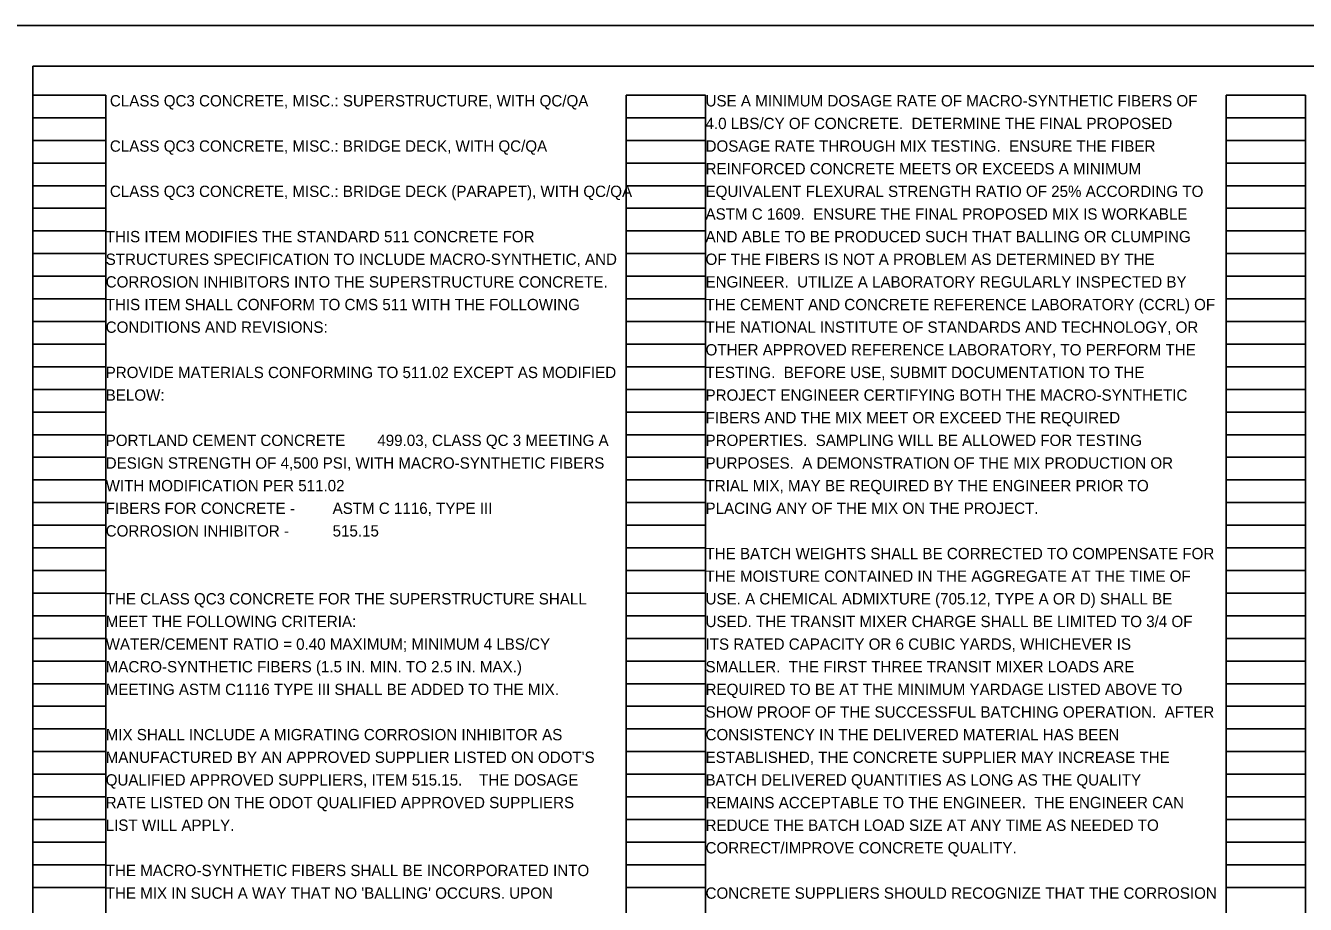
# Model space of a CAD drawing. Extents: x -14.8 to 34, y 0 to 43.2.
# Drawn here: x 1.91 to 17.74, y 11.13 to 22 of the extents above; entities that cross this region are included whole.
import ezdxf

# ---------------------------------------------------------------- set-up
doc = ezdxf.new("R2010")
doc.units = 0
for name, color, linetype in [('SH_Border', 7, 'Continuous'), ('SH_Cut_Line', 7, 'Continuous'), ('SH_Data', 7, 'Continuous'), ('SH_Text', 7, 'Continuous')]:
    doc.layers.add(name, color=color, linetype=linetype)

msp = doc.modelspace()

# ---------------------------------------------------------------- linework, layer by layer
at = {"layer": 'SH_Border'}
msp.add_lwpolyline([(2, 21.5), (33.5, 21.5), (33.5, 0.5), (2, 0.5)], close=True, dxfattribs=at)
at = {"layer": 'SH_Cut_Line'}
msp.add_lwpolyline([(0, 22), (34, 22), (34, 0), (0, 0)], close=True, dxfattribs=at)
at = {"layer": 'SH_Data'}
for p, q in [((2, 0.98), (2, 21.14)), ((2, 21.14), (2.9, 21.14)), ((2.9, 0.98), (2.9, 21.14)), ((9.34, 0.98), (9.34, 21.14)), ((9.34, 21.14), (10.32, 21.14)), ((10.32, 0.98), (10.32, 21.14)), ((16.76, 0.98), (16.76, 21.14)), ((16.76, 21.14), (17.74, 21.14)), ((17.74, 0.98), (17.74, 21.14)), ((2, 20.86), (2.9, 20.86)), ((9.34, 20.86), (10.32, 20.86)), ((16.76, 20.86), (17.74, 20.86)), ((2, 20.58), (2.9, 20.58)), ((9.34, 20.58), (10.32, 20.58)), ((16.76, 20.58), (17.74, 20.58)), ((2, 20.3), (2.9, 20.3)), ((9.34, 20.3), (10.32, 20.3)), ((16.76, 20.3), (17.74, 20.3)), ((2, 20.02), (2.9, 20.02)), ((9.34, 20.02), (10.32, 20.02)), ((16.76, 20.02), (17.74, 20.02)), ((2, 19.74), (2.9, 19.74)), ((9.34, 19.74), (10.32, 19.74)), ((16.76, 19.74), (17.74, 19.74)), ((2, 19.46), (2.9, 19.46)), ((9.34, 19.46), (10.32, 19.46)), ((16.76, 19.46), (17.74, 19.46)), ((2, 19.18), (2.9, 19.18)), ((9.34, 19.18), (10.32, 19.18)), ((16.76, 19.18), (17.74, 19.18)), ((2, 18.9), (2.9, 18.9)), ((9.34, 18.9), (10.32, 18.9)), ((16.76, 18.9), (17.74, 18.9)), ((2, 18.62), (2.9, 18.62)), ((9.34, 18.62), (10.32, 18.62)), ((16.76, 18.62), (17.74, 18.62)), ((2, 18.34), (2.9, 18.34)), ((9.34, 18.34), (10.32, 18.34)), ((16.76, 18.34), (17.74, 18.34)), ((2, 18.06), (2.9, 18.06)), ((9.34, 18.06), (10.32, 18.06)), ((16.76, 18.06), (17.74, 18.06)), ((2, 17.78), (2.9, 17.78)), ((9.34, 17.78), (10.32, 17.78)), ((16.76, 17.78), (17.74, 17.78)), ((2, 17.5), (2.9, 17.5)), ((9.34, 17.5), (10.32, 17.5)), ((16.76, 17.5), (17.74, 17.5)), ((2, 17.22), (2.9, 17.22)), ((9.34, 17.22), (10.32, 17.22)), ((16.76, 17.22), (17.74, 17.22)), ((2, 16.94), (2.9, 16.94)), ((9.34, 16.94), (10.32, 16.94)), ((16.76, 16.94), (17.74, 16.94)), ((2, 16.66), (2.9, 16.66)), ((9.34, 16.66), (10.32, 16.66)), ((16.76, 16.66), (17.74, 16.66)), ((2, 16.38), (2.9, 16.38)), ((9.34, 16.38), (10.32, 16.38)), ((16.76, 16.38), (17.74, 16.38)), ((2, 16.1), (2.9, 16.1)), ((9.34, 16.1), (10.32, 16.1)), ((16.76, 16.1), (17.74, 16.1)), ((2, 15.82), (2.9, 15.82)), ((9.34, 15.82), (10.32, 15.82)), ((16.76, 15.82), (17.74, 15.82)), ((2, 15.54), (2.9, 15.54)), ((9.34, 15.54), (10.32, 15.54)), ((16.76, 15.54), (17.74, 15.54)), ((2, 15.26), (2.9, 15.26)), ((9.34, 15.26), (10.32, 15.26)), ((16.76, 15.26), (17.74, 15.26)), ((2, 14.98), (2.9, 14.98)), ((9.34, 14.98), (10.32, 14.98)), ((16.76, 14.98), (17.74, 14.98)), ((2, 14.7), (2.9, 14.7)), ((9.34, 14.7), (10.32, 14.7)), ((16.76, 14.7), (17.74, 14.7)), ((2, 14.42), (2.9, 14.42)), ((9.34, 14.42), (10.32, 14.42)), ((16.76, 14.42), (17.74, 14.42)), ((2, 14.14), (2.9, 14.14)), ((9.34, 14.14), (10.32, 14.14)), ((16.76, 14.14), (17.74, 14.14)), ((2, 13.86), (2.9, 13.86)), ((9.34, 13.86), (10.32, 13.86)), ((16.76, 13.86), (17.74, 13.86)), ((2, 13.58), (2.9, 13.58)), ((9.34, 13.58), (10.32, 13.58)), ((16.76, 13.58), (17.74, 13.58)), ((2, 13.3), (2.9, 13.3)), ((9.34, 13.3), (10.32, 13.3)), ((16.76, 13.3), (17.74, 13.3)), ((2, 13.02), (2.9, 13.02)), ((9.34, 13.02), (10.32, 13.02)), ((16.76, 13.02), (17.74, 13.02)), ((2, 12.74), (2.9, 12.74)), ((9.34, 12.74), (10.32, 12.74)), ((16.76, 12.74), (17.74, 12.74)), ((2, 12.46), (2.9, 12.46)), ((9.34, 12.46), (10.32, 12.46)), ((16.76, 12.46), (17.74, 12.46)), ((2, 12.18), (2.9, 12.18)), ((9.34, 12.18), (10.32, 12.18)), ((16.76, 12.18), (17.74, 12.18)), ((2, 11.9), (2.9, 11.9)), ((9.34, 11.9), (10.32, 11.9)), ((16.76, 11.9), (17.74, 11.9)), ((2, 11.62), (2.9, 11.62)), ((9.34, 11.62), (10.32, 11.62)), ((16.76, 11.62), (17.74, 11.62)), ((2, 11.34), (2.9, 11.34)), ((9.34, 11.34), (10.32, 11.34)), ((16.76, 11.34), (17.74, 11.34))]:
    msp.add_line(p, q, dxfattribs=at)

# ---------------------------------------------------------------- texts
at = {"layer": 'SH_Text'}
for s, p in [('CLASS QC3 CONCRETE, MISC.: SUPERSTRUCTURE, WITH QC/QA', (2.952, 21)), ('USE A MINIMUM DOSAGE RATE OF MACRO-SYNTHETIC FIBERS OF ', (10.32, 21)), ('4.0 LBS/CY OF CONCRETE.  DETERMINE THE FINAL PROPOSED ', (10.32, 20.72)), ('CLASS QC3 CONCRETE, MISC.: BRIDGE DECK, WITH QC/QA', (2.952, 20.44)), ('DOSAGE RATE THROUGH MIX TESTING.  ENSURE THE FIBER ', (10.32, 20.44)), ('REINFORCED CONCRETE MEETS OR EXCEEDS A MINIMUM ', (10.32, 20.16)), ('CLASS QC3 CONCRETE, MISC.: BRIDGE DECK (PARAPET), WITH QC/QA', (2.952, 19.88)), ('EQUIVALENT FLEXURAL STRENGTH RATIO OF 25% ACCORDING TO ', (10.32, 19.88)), ('ASTM C 1609.  ENSURE THE FINAL PROPOSED MIX IS WORKABLE ', (10.32, 19.6)), ('THIS ITEM MODIFIES THE STANDARD 511 CONCRETE FOR ', (2.9, 19.32)), ('AND ABLE TO BE PRODUCED SUCH THAT BALLING OR CLUMPING ', (10.32, 19.32)), ('STRUCTURES SPECIFICATION TO INCLUDE MACRO-SYNTHETIC, AND ', (2.9, 19.04)), ('OF THE FIBERS IS NOT A PROBLEM AS DETERMINED BY THE ', (10.32, 19.04)), ('CORROSION INHIBITORS INTO THE SUPERSTRUCTURE CONCRETE.  ', (2.9, 18.76)), ('ENGINEER.  UTILIZE A LABORATORY REGULARLY INSPECTED BY ', (10.32, 18.76)), ('THIS ITEM SHALL CONFORM TO CMS 511 WITH THE FOLLOWING ', (2.9, 18.48)), ('THE CEMENT AND CONCRETE REFERENCE LABORATORY (CCRL) OF ', (10.32, 18.48)), ('CONDITIONS AND REVISIONS:', (2.9, 18.2)), ('THE NATIONAL INSTITUTE OF STANDARDS AND TECHNOLOGY, OR ', (10.32, 18.2)), ('OTHER APPROVED REFERENCE LABORATORY, TO PERFORM THE ', (10.32, 17.92)), ('PROVIDE MATERIALS CONFORMING TO 511.02 EXCEPT AS MODIFIED ', (2.9, 17.64)), ('TESTING.  BEFORE USE, SUBMIT DOCUMENTATION TO THE ', (10.32, 17.64)), ('BELOW:', (2.9, 17.36)), ('PROJECT ENGINEER CERTIFYING BOTH THE MACRO-SYNTHETIC ', (10.32, 17.36)), ('FIBERS AND THE MIX MEET OR EXCEED THE REQUIRED ', (10.32, 17.08)), ('PORTLAND CEMENT CONCRETE', (2.9, 16.8)), ('499.03, CLASS QC 3 MEETING A ', (6.26, 16.8)), ('PROPERTIES.  SAMPLING WILL BE ALLOWED FOR TESTING ', (10.32, 16.8)), ('DESIGN STRENGTH OF 4,500 PSI, WITH MACRO-SYNTHETIC FIBERS ', (2.9, 16.52)), ('PURPOSES.  A DEMONSTRATION OF THE MIX PRODUCTION OR ', (10.32, 16.52)), ('WITH MODIFICATION PER 511.02', (2.9, 16.24)), ('TRIAL MIX, MAY BE REQUIRED BY THE ENGINEER PRIOR TO ', (10.32, 16.24)), ('FIBERS FOR CONCRETE -', (2.9, 15.96)), ('ASTM C 1116, TYPE III', (5.707, 15.96)), ('PLACING ANY OF THE MIX ON THE PROJECT.  ', (10.32, 15.96)), ('CORROSION INHIBITOR -', (2.9, 15.68)), ('515.15', (5.707, 15.68)), ('THE BATCH WEIGHTS SHALL BE CORRECTED TO COMPENSATE FOR ', (10.32, 15.4)), ('THE MOISTURE CONTAINED IN THE AGGREGATE AT THE TIME OF ', (10.32, 15.12)), ('THE CLASS QC3 CONCRETE FOR THE SUPERSTRUCTURE SHALL ', (2.9, 14.84)), ('USE. A CHEMICAL ADMIXTURE (705.12, TYPE A OR D) SHALL BE ', (10.32, 14.84)), ('MEET THE FOLLOWING CRITERIA:', (2.9, 14.56)), ('USED. THE TRANSIT MIXER CHARGE SHALL BE LIMITED TO 3/4 OF ', (10.32, 14.56)), ('WATER/CEMENT RATIO = 0.40 MAXIMUM; MINIMUM 4 LBS/CY ', (2.9, 14.28)), ('ITS RATED CAPACITY OR 6 CUBIC YARDS, WHICHEVER IS ', (10.32, 14.28)), ('MACRO-SYNTHETIC FIBERS (1.5 IN. MIN. TO 2.5 IN. MAX.) ', (2.9, 14)), ('SMALLER.  THE FIRST THREE TRANSIT MIXER LOADS ARE ', (10.32, 14)), ('MEETING ASTM C1116 TYPE III SHALL BE ADDED TO THE MIX.', (2.9, 13.72)), ('REQUIRED TO BE AT THE MINIMUM YARDAGE LISTED ABOVE TO ', (10.32, 13.72)), ('SHOW PROOF OF THE SUCCESSFUL BATCHING OPERATION.  AFTER ', (10.32, 13.44)), ('MIX SHALL INCLUDE A MIGRATING CORROSION INHIBITOR AS ', (2.9, 13.16)), ('CONSISTENCY IN THE DELIVERED MATERIAL HAS BEEN ', (10.32, 13.16)), ("MANUFACTURED BY AN APPROVED SUPPLIER LISTED ON ODOT'S ", (2.9, 12.88)), ('ESTABLISHED, THE CONCRETE SUPPLIER MAY INCREASE THE ', (10.32, 12.88)), ('QUALIFIED APPROVED SUPPLIERS, ITEM 515.15.    THE DOSAGE ', (2.9, 12.6)), ('BATCH DELIVERED QUANTITIES AS LONG AS THE QUALITY ', (10.32, 12.6)), ('RATE LISTED ON THE ODOT QUALIFIED APPROVED SUPPLIERS ', (2.9, 12.32)), ('REMAINS ACCEPTABLE TO THE ENGINEER.  THE ENGINEER CAN ', (10.32, 12.32)), ('LIST WILL APPLY.  ', (2.9, 12.04)), ('REDUCE THE BATCH LOAD SIZE AT ANY TIME AS NEEDED TO ', (10.32, 12.04)), ('CORRECT/IMPROVE CONCRETE QUALITY.', (10.32, 11.76)), ('THE MACRO-SYNTHETIC FIBERS SHALL BE INCORPORATED INTO ', (2.9, 11.48)), ("THE MIX IN SUCH A WAY THAT NO 'BALLING' OCCURS. UPON ", (2.9, 11.2)), ('CONCRETE SUPPLIERS SHOULD RECOGNIZE THAT THE CORROSION ', (10.32, 11.2))]:
    msp.add_text(s, height=0.14, dxfattribs=at).set_placement(p)

doc.saveas('drawing.dxf')
